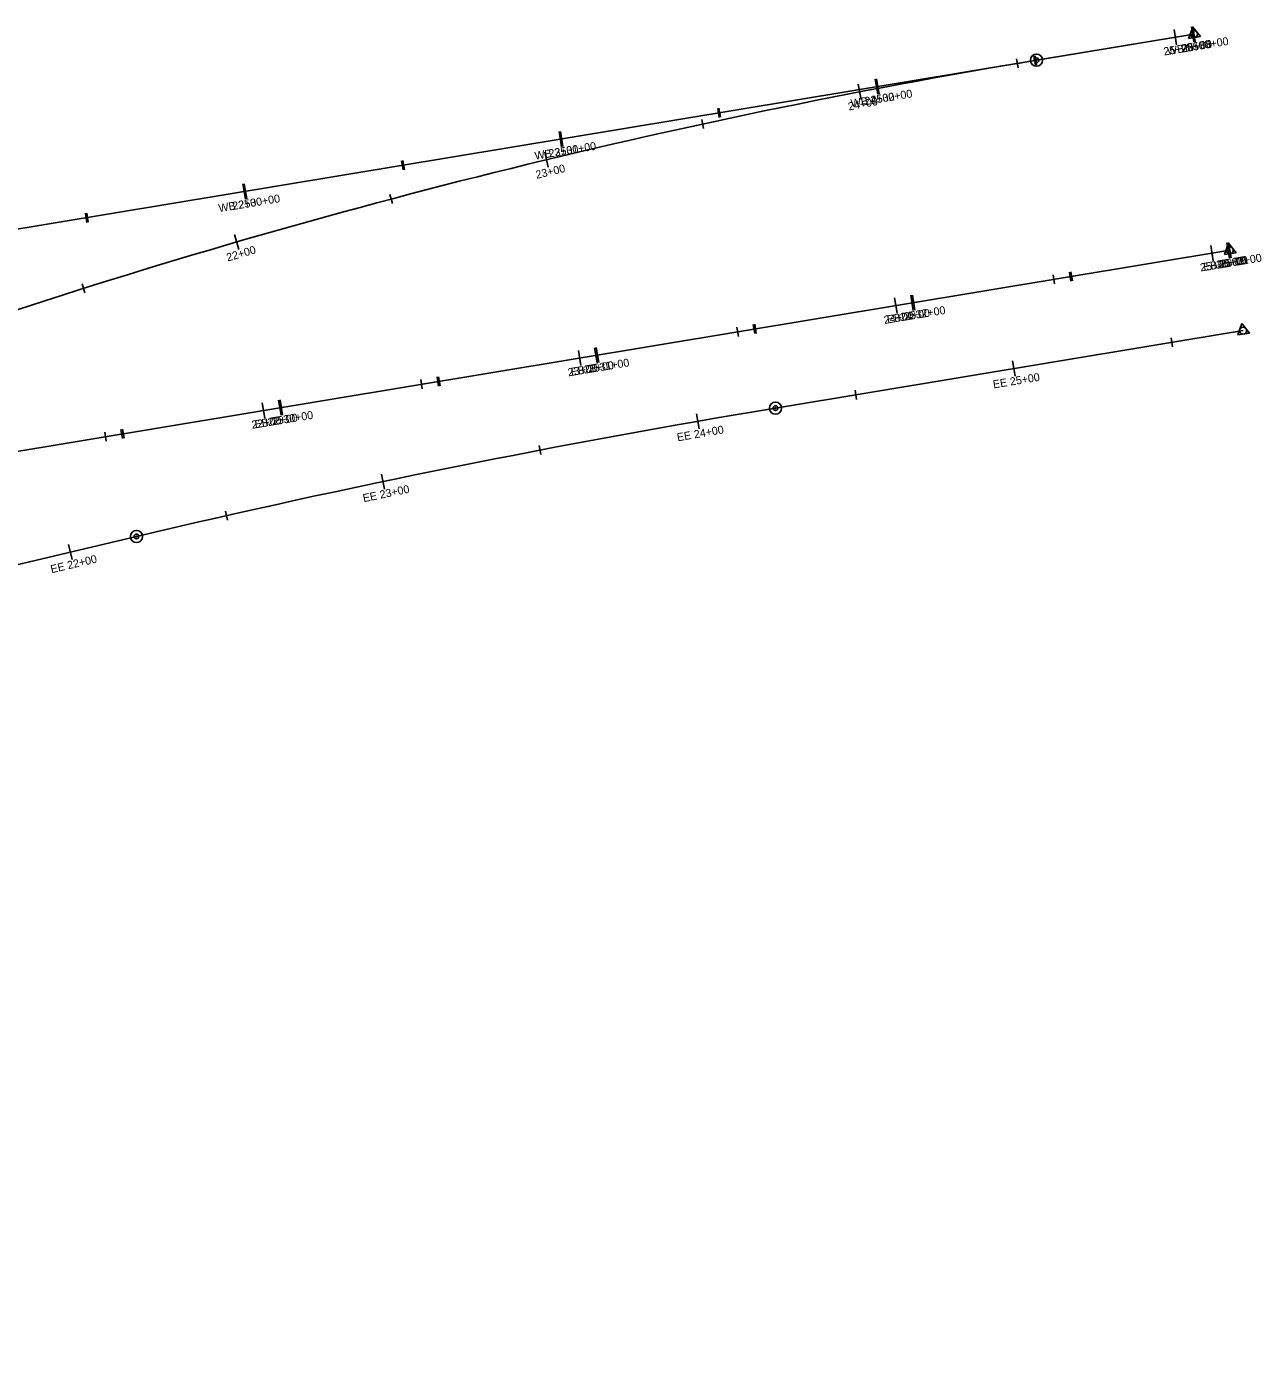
# Model space of a CAD drawing. Extents: x 950864 to 953360, y 1126381 to 1128045.
# Drawn here: x 952974.5 to 953359.9, y 1127119 to 1127532.4 of the extents above; entities that cross this region are included whole.
import ezdxf

# ---------------------------------------------------------------- set-up
doc = ezdxf.new("R2010")
doc.units = 0
for name, color, linetype in [('Existing', 7, 'Continuous'), ('LFILL_P', 7, 'Continuous'), ('North Crossover', 7, 'Continuous')]:
    doc.layers.add(name, color=color, linetype=linetype)

msp = doc.modelspace()

# ---------------------------------------------------------------- linework, layer by layer
at = {"layer": 'Existing'}
for p, q in [((950872.52, 1127121.15), (953338.85, 1127530.05)), ((950883.69, 1127053.72), (953350.03, 1127462.62)), ((953208.27, 1127413.36), (953354.18, 1127437.55)), ((952548.55, 1127264.51), (953008.86, 1127373.31))]:
    msp.add_line(p, q, dxfattribs=at)
for points in [[(953337.16, 1127528.66), (953338.49, 1127532.19)], [(953338.46, 1127532.41), (953339.24, 1127527.68)], [(953338.49, 1127532.19), (953340.89, 1127529.28)], [(953340.89, 1127529.28), (953337.16, 1127528.66)], [(953289.29, 1127523.29), (953289.76, 1127520.45)], [(953239.8, 1127516.06), (953240.59, 1127511.32)], [(953190.63, 1127506.93), (953191.11, 1127504.09)], [(953141.15, 1127499.7), (953141.94, 1127494.97)], [(953091.98, 1127490.58), (953092.45, 1127487.74)], [(953042.5, 1127483.35), (953043.28, 1127478.61)], [(952993.33, 1127474.22), (952993.8, 1127471.38)], [(953348.34, 1127461.23), (953349.67, 1127464.77)], [(953349.64, 1127464.99), (953350.42, 1127460.25)], [(953349.67, 1127464.77), (953352.07, 1127461.85)], [(953352.07, 1127461.85), (953348.34, 1127461.23)], [(953300.47, 1127455.86), (953300.94, 1127453.02)], [(953250.98, 1127448.63), (953251.77, 1127443.89)], [(953201.81, 1127439.5), (953202.28, 1127436.66)], [(953352.5, 1127436.17), (953353.83, 1127439.7)], [(953353.83, 1127439.7), (953356.23, 1127436.78)], [(953331.73, 1127435.29), (953332.2, 1127432.45)], [(953356.23, 1127436.78), (953352.5, 1127436.17)], [(953152.33, 1127432.27), (953153.11, 1127427.54)], [(953282.25, 1127428.06), (953283.03, 1127423.32)], [(953103.16, 1127423.15), (953103.63, 1127420.31)], [(953233.08, 1127418.93), (953233.55, 1127416.09)], [(953053.68, 1127415.92), (953054.46, 1127411.18)], [(953183.59, 1127411.6), (953184.41, 1127406.87)], [(953004.51, 1127406.79), (953004.98, 1127403.95)], [(953134.55, 1127401.66), (953135.09, 1127398.83)], [(953085.3, 1127392.78), (953086.28, 1127388.08)], [(953036.61, 1127381.21), (953037.25, 1127378.4)], [(952987.69, 1127370.78), (952988.79, 1127366.1)]]:
    msp.add_lwpolyline(points, dxfattribs=at)
for centre, radius in [((953338.85, 1127530.05), 1.09), ((953350.03, 1127462.62), 1.09), ((953354.19, 1127437.55), 1.09), ((953208.27, 1127413.36), 1.89), ((953208.27, 1127413.36), 0.744), ((953208.27, 1127413.36), 0.154), ((953008.86, 1127373.31), 1.88), ((953008.86, 1127373.31), 0.747), ((953008.86, 1127373.31), 0.156)]:
    msp.add_circle(centre, radius, dxfattribs=at)
msp.add_arc((953698.94, 1124453.76), 3000, 99.4135, 103.29873, dxfattribs=at)
at = {"layer": 'LFILL_P'}
for p, q in [((953289.7, 1127521.9), (953338.85, 1127530.05)), ((952923.92, 1127391.97), (953350.03, 1127462.62))]:
    msp.add_line(p, q, dxfattribs=at)
for points in [[(953332.67, 1127531.45), (953333.45, 1127526.72)], [(953337.16, 1127528.66), (953338.49, 1127532.19)], [(953338.46, 1127532.41), (953339.24, 1127527.68)], [(953338.46, 1127532.41), (953339.24, 1127527.68)], [(953338.49, 1127532.19), (953340.89, 1127529.28)], [(953340.89, 1127529.28), (953337.16, 1127528.66)], [(953283.5, 1127522.32), (953283.97, 1127519.48)], [(953234.08, 1127514.37), (953234.99, 1127509.66)], [(953185.24, 1127503.4), (953185.85, 1127500.59)], [(953136.24, 1127493.18), (953137.37, 1127488.52)], [(953087.97, 1127479.97), (953088.71, 1127477.19)], [(953039.49, 1127467.5), (953040.83, 1127462.89)], [(953348.34, 1127461.23), (953349.67, 1127464.77)], [(953349.14, 1127464.9), (953349.93, 1127460.17)], [(953349.64, 1127464.99), (953350.42, 1127460.25)], [(953349.64, 1127464.99), (953350.42, 1127460.25)], [(953349.67, 1127464.77), (953352.07, 1127461.85)], [(953352.07, 1127461.85), (953348.34, 1127461.23)], [(952991.88, 1127452.08), (952992.74, 1127449.33)], [(953299.97, 1127455.78), (953300.44, 1127452.94)], [(953250.49, 1127448.55), (953251.27, 1127443.81)], [(953201.32, 1127439.42), (953201.79, 1127436.58)], [(953151.83, 1127432.19), (953152.62, 1127427.46)], [(953102.67, 1127423.07), (953103.14, 1127420.23)], [(953053.18, 1127415.84), (953053.97, 1127411.1)], [(953004.01, 1127406.71), (953004.48, 1127403.87)]]:
    msp.add_lwpolyline(points, dxfattribs=at)
for centre, radius in [((953338.85, 1127530.05), 1.09), ((953289.71, 1127521.9), 1.89), ((953289.71, 1127521.9), 0.744), ((953289.71, 1127521.9), 0.154), ((953350.03, 1127462.62), 1.09)]:
    msp.add_circle(centre, radius, dxfattribs=at)
msp.add_arc((953643.81, 1125386.05), 2165, 99.4135, 108.56188, dxfattribs=at)
at = {"layer": 'North Crossover'}
for p, q in [((952650.04, 1127415.85), (953338.85, 1127530.05)), ((952769.27, 1127366.33), (953350.03, 1127462.62))]:
    msp.add_line(p, q, dxfattribs=at)
for points in [[(953337.16, 1127528.66), (953338.49, 1127532.19)], [(953338.06, 1127532.35), (953338.84, 1127527.61)], [(953338.46, 1127532.41), (953339.24, 1127527.68)], [(953338.46, 1127532.41), (953339.24, 1127527.68)], [(953338.49, 1127532.19), (953340.89, 1127529.28)], [(953340.89, 1127529.28), (953337.16, 1127528.66)], [(953288.89, 1127523.22), (953289.36, 1127520.38)], [(953239.4, 1127515.99), (953240.19, 1127511.26)], [(953190.23, 1127506.87), (953190.71, 1127504.03)], [(953140.75, 1127499.64), (953141.54, 1127494.9)], [(953091.58, 1127490.51), (953092.05, 1127487.67)], [(953042.1, 1127483.28), (953042.88, 1127478.54)], [(952992.93, 1127474.15), (952993.4, 1127471.31)], [(953348.34, 1127461.23), (953349.67, 1127464.77)], [(953349.64, 1127464.99), (953350.42, 1127460.25)], [(953349.64, 1127464.99), (953350.42, 1127460.25)], [(953349.67, 1127464.77), (953352.07, 1127461.85)], [(953344.07, 1127464.06), (953344.85, 1127459.33)], [(953352.07, 1127461.85), (953348.34, 1127461.23)], [(953294.9, 1127454.94), (953295.37, 1127452.1)], [(953245.42, 1127447.71), (953246.2, 1127442.97)], [(953196.25, 1127438.58), (953196.72, 1127435.74)], [(953146.76, 1127431.35), (953147.55, 1127426.62)], [(953097.59, 1127422.23), (953098.06, 1127419.39)], [(953048.11, 1127415), (953048.89, 1127410.26)], [(952998.94, 1127405.87), (952999.41, 1127403.03)]]:
    msp.add_lwpolyline(points, dxfattribs=at)
for centre in [(953338.85, 1127530.05), (953350.03, 1127462.62)]:
    msp.add_circle(centre, 1.09, dxfattribs=at)

# ---------------------------------------------------------------- texts
at = {"layer": 'Existing'}
for s, rotation, p in [('WB 2533+00', 9.4135, (953330.68, 1127523.53)), ('WB 2532+00', 9.4135, (953231.99, 1127507.17)), ('WB 2531+00', 9.4135, (953133.33, 1127490.82)), ('WB 2530+00', 9.4135, (953034.68, 1127474.46)), ('EB 2533+00', 9.4135, (953341.94, 1127456.12)), ('EB 2532+00', 9.4135, (953243.25, 1127439.76)), ('EB 2531+00', 9.4135, (953144.59, 1127423.4)), ('EE 25+00', 9.4135, (953276.34, 1127419.49)), ('EB 2530+00', 9.4135, (953045.94, 1127407.05)), ('EE 24+00', 9.8836, (953177.74, 1127402.98)), ('EE 23+00', 11.7935, (953079.78, 1127383.98)), ('EE 22+00', 13.2987, (952982.37, 1127361.82))]:
    msp.add_text(s, height=2.496, rotation=rotation, dxfattribs=at).set_placement(p)
at = {"layer": 'LFILL_P'}
for s, rotation, p in [('25+00', 9.4135, (953329.56, 1127523.35)), ('25+06', 9.4135, (953335.37, 1127524.31)), ('25+06', 9.4135, (953335.37, 1127524.31)), ('24+00', 10.8969, (953231.17, 1127506.19)), ('23+00', 13.5434, (953133.75, 1127484.88)), ('22+00', 16.1898, (953037.35, 1127459.08)), ('25+00', 9.4135, (953346.03, 1127456.8)), ('25+01', 9.4135, (953346.76, 1127456.92)), ('25+01', 9.4135, (953346.76, 1127456.92)), ('24+00', 9.4135, (953247.37, 1127440.44)), ('23+00', 9.4135, (953148.75, 1127424.09)), ('22+00', 9.4135, (953050.06, 1127407.73))]:
    msp.add_text(s, height=2.496, rotation=rotation, dxfattribs=at).set_placement(p)
at = {"layer": 'North Crossover'}
for s, p in [('25+00', (953334.95, 1127524.24)), ('25+00', (953335.34, 1127524.31)), ('25+00', (953335.34, 1127524.31)), ('24+00', (953236.28, 1127507.88)), ('23+00', (953137.67, 1127491.53)), ('22+00', (953038.98, 1127475.17)), ('25+06', (953346.55, 1127456.88)), ('25+06', (953346.55, 1127456.88)), ('25+00', (953340.96, 1127455.96)), ('24+00', (953242.3, 1127439.6)), ('23+00', (953143.68, 1127423.25)), ('22+00', (953044.99, 1127406.89))]:
    msp.add_text(s, height=2.496, rotation=9.4135, dxfattribs=at).set_placement(p)

doc.saveas('drawing.dxf')
